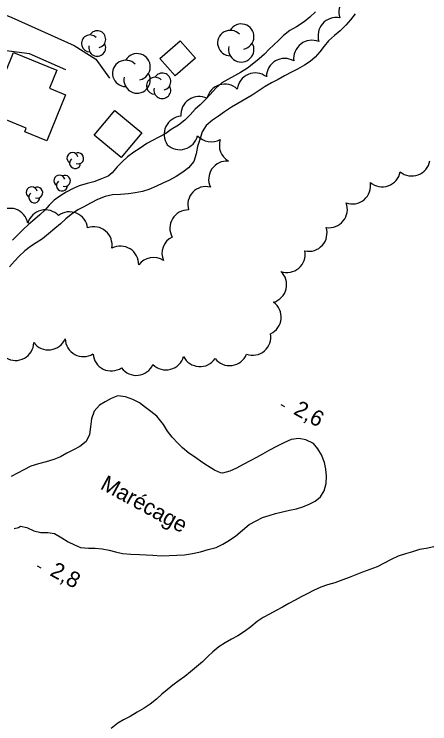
# Model space of a CAD drawing. Extents: x 219136 to 222520, y 5421589 to 5424530.
# Drawn here: x 220438.7 to 220517.5, y 5422818.4 to 5422953.1 of the extents above; entities that cross this region are included whole.
import ezdxf

# ---------------------------------------------------------------- set-up
doc = ezdxf.new("R2010")
doc.units = 0
for name, color, linetype in [('Level 19', 7, 'Continuous'), ('Level 2', 7, 'Continuous'), ('Level 3', 7, 'Continuous'), ('Level 31', 7, 'Continuous'), ('Level 4', 7, 'Continuous'), ('Level 44', 7, 'Continuous'), ('Level 7', 7, 'Continuous')]:
    doc.layers.add(name, color=color, linetype=linetype)

msp = doc.modelspace()

# ---------------------------------------------------------------- linework, layer by layer
at = {"layer": 'Level 19'}
for points in [[(220447.7, 5422966.82), (220446.62, 5422967.06), (220444.01, 5422965.73), (220441.58, 5422962.38), (220440.51, 5422959.82), (220439.56, 5422957.04), (220436.98, 5422955.8), (220434.73, 5422954.86), (220435.39, 5422953.58), (220438.23, 5422952.4), (220450.02, 5422947.09), (220454.18, 5422944.5), (220456.75, 5422940.92)], [(220448.49, 5422942.48), (220441.58, 5422945.53), (220436.18, 5422946.26), (220433.12, 5422945.86), (220429.86, 5422946.73)]]:
    msp.add_lwpolyline(points, dxfattribs=at)
at = {"layer": 'Level 2'}
for points in [[(220495.8, 5422953.51), (220494.73, 5422952.49), (220493.67, 5422951.59), (220492.19, 5422950.64), (220490.9, 5422949.94), (220489.74, 5422949.01), (220488.81, 5422948.12), (220487.89, 5422947.25), (220486.97, 5422946.35), (220486.09, 5422945.46), (220485.08, 5422944.61), (220484.1, 5422943.79), (220482.89, 5422942.81), (220481.56, 5422941.97), (220480.41, 5422941.34), (220479.18, 5422940.68), (220478.03, 5422940.04), (220476.87, 5422939.01), (220475.83, 5422937.83), (220474.94, 5422936.84), (220473.91, 5422935.87), (220472.98, 5422935.01), (220472.06, 5422933.99), (220471.03, 5422932.93), (220469.81, 5422932.02), (220468.46, 5422931.19), (220467.39, 5422930.45), (220466.07, 5422929.74), (220464.92, 5422929.12), (220463.83, 5422928.52), (220462.55, 5422927.64), (220461.37, 5422926.88), (220460.16, 5422925.97), (220459.13, 5422925.02), (220458.21, 5422924.09), (220457.22, 5422922.97), (220456.5, 5422922.35), (220455.2, 5422921.82), (220453.78, 5422921.28), (220452.5, 5422920.92), (220451.01, 5422920.5), (220449.85, 5422919.99), (220448.51, 5422919.28), (220447.35, 5422918.51), (220446.28, 5422917.76), (220445.31, 5422916.81), (220444.46, 5422915.85), (220443.56, 5422914.96), (220442.58, 5422914.14), (220441.39, 5422913.17), (220440.31, 5422912.16), (220439.39, 5422911.22)], [(220503.32, 5422953.13), (220502.42, 5422951.99), (220501.51, 5422950.98), (220500.48, 5422949.92), (220499.4, 5422948.99), (220498.25, 5422947.99), (220497.44, 5422946.96), (220496.59, 5422945.94), (220495.71, 5422944.93), (220494.8, 5422944.05)], [(220494.8, 5422944.05), (220493.7, 5422943.38), (220492.35, 5422942.65), (220491.21, 5422942.04), (220489.91, 5422941.34), (220488.71, 5422940.69), (220487.46, 5422940.02), (220486.24, 5422939.36), (220484.93, 5422938.48), (220483.77, 5422937.71), (220482.57, 5422936.97), (220481.07, 5422936.09), (220479.86, 5422935.44), (220478.53, 5422934.55), (220477.38, 5422933.7), (220476.24, 5422932.92), (220475.08, 5422931.95), (220474.32, 5422930.72), (220473.86, 5422929.29), (220473.43, 5422927.97), (220473.14, 5422926.55), (220472.74, 5422925.1), (220471.73, 5422923.92), (220470.67, 5422923.08), (220469.37, 5422922.27), (220468.09, 5422921.59), (220466.86, 5422920.98), (220465.62, 5422920.4), (220464.2, 5422919.8), (220462.97, 5422919.43), (220461.58, 5422919.17), (220460.32, 5422919), (220458.81, 5422918.84), (220457.3, 5422918.81), (220455.92, 5422918.48), (220454.48, 5422917.92), (220453.11, 5422917.21), (220451.85, 5422916.53), (220450.73, 5422915.91), (220449.49, 5422915.07), (220448.44, 5422914.21), (220447.44, 5422913.31), (220446.39, 5422912.38), (220445.15, 5422911.36), (220444.01, 5422910.44), (220442.84, 5422909.7), (220441.79, 5422909.01), (220440.7, 5422908.14), (220439.59, 5422907.12), (220438.73, 5422906.2), (220437.8, 5422905.14)], [(220439.39, 5422911.22), (220438.37, 5422910.16)]]:
    msp.add_lwpolyline(points, dxfattribs=at)
at = {"layer": 'Level 3'}
for p, q in [((220489.2, 5422879.03), (220489.9, 5422878.64)), ((220443.02, 5422848.42), (220443.72, 5422848.04))]:
    msp.add_line(p, q, dxfattribs=at)
at = {"layer": 'Level 31'}
for points in [[(220473.05, 5422944.73), (220469.19, 5422941.36), (220466.31, 5422944.66), (220470.16, 5422948.03)], [(220433.87, 5422934.35), (220438.55, 5422945.77), (220446.74, 5422942.41), (220445.35, 5422939.04), (220448.43, 5422937.77), (220444.83, 5422929.02), (220440.68, 5422930.72), (220440.97, 5422931.43)], [(220462.86, 5422930.57), (220458.94, 5422925.85), (220453.84, 5422930.1), (220457.76, 5422934.81)]]:
    msp.add_lwpolyline(points, close=True, dxfattribs=at)
at = {"layer": 'Level 4'}
for points in [[(220518.21, 5422851.98), (220516.76, 5422851.72), (220515.49, 5422851.47), (220514.16, 5422851.08), (220512.84, 5422850.67), (220511.48, 5422850.21), (220510.16, 5422849.6), (220508.81, 5422848.88), (220507.46, 5422848.2), (220506.06, 5422847.71), (220504.7, 5422847.22), (220503.41, 5422846.71), (220502.19, 5422846.21), (220500.98, 5422845.74), (220499.48, 5422845.2), (220498.09, 5422844.79), (220496.8, 5422844.36), (220495.44, 5422843.75), (220494.31, 5422843.16), (220493.09, 5422842.5), (220491.95, 5422841.89), (220490.76, 5422841.24), (220489.52, 5422840.58), (220488.32, 5422839.94), (220487.08, 5422839.26), (220485.86, 5422838.58), (220484.73, 5422837.81)], [(220484.73, 5422837.81), (220483.56, 5422836.86), (220482.34, 5422835.95), (220481.06, 5422835.12), (220479.87, 5422834.46), (220478.68, 5422833.82), (220477.44, 5422833.06), (220476.31, 5422832.08), (220475.41, 5422831.18), (220474.37, 5422830.22), (220473.21, 5422829.24), (220472.09, 5422828.31), (220471.05, 5422827.43), (220469.96, 5422826.62), (220468.77, 5422825.77), (220467.65, 5422824.87), (220466.66, 5422824.04), (220465.62, 5422823.12), (220464.43, 5422822.13), (220463.34, 5422821.38), (220461.99, 5422820.63), (220460.63, 5422819.85), (220459.42, 5422819.2), (220458.31, 5422818.53), (220457.07, 5422817.55)]]:
    msp.add_lwpolyline(points, dxfattribs=at)
at = {"layer": 'Level 44'}
for centre, radius, start, end in [((220503.67, 5422953.47), 3.46, 78.6697, 198.6697), ((220481.71, 5422948.79), 2.41, 282.2692, 149.7262), ((220499.72, 5422948.97), 3.46, 78.8019, 198.8019), ((220454.41, 5422948.3), 1.61, 282.2692, 149.7262), ((220479.64, 5422947.58), 2.41, 44.1153, 269.8039), ((220453.03, 5422947.5), 1.61, 44.1153, 269.8039), ((220454.41, 5422946.69), 1.61, 166.9368, 29.6212), ((220481.71, 5422946.38), 2.41, 166.9368, 29.6212), ((220495.11, 5422944.65), 3.46, 67.3897, 187.3897), ((220461.97, 5422943.07), 2.5, 282.2692, 149.7262), ((220489.94, 5422941.2), 3.46, 60.0102, 180.0102), ((220459.82, 5422941.82), 2.5, 44.1153, 269.8039), ((220461.97, 5422940.56), 2.5, 166.9368, 29.6212), ((220466.75, 5422940.27), 1.61, 282.2692, 149.7262), ((220484.39, 5422938.44), 3.46, 53.0049, 173.0049), ((220465.37, 5422939.47), 1.61, 44.1153, 269.8039), ((220466.75, 5422938.66), 1.61, 166.9368, 29.6212), ((220478.59, 5422936.33), 3.46, 47.0027, 167.0027), ((220473.73, 5422933.98), 3.46, 64.5457, 184.5457), ((220470.54, 5422930.25), 3.46, 94.3395, 214.3395), ((220470.06, 5422930.81), 3.46, 226.5012, 346.5012), ((220476.03, 5422932.29), 3.46, 221.4231, 299.6204), ((220481.02, 5422928.18), 3.46, 161.4231, 239.6204), ((220449.73, 5422925.74), 1.05, 14.9746, 237.6589), ((220450.22, 5422924.82), 1.05, 130.3069, 357.764), ((220450.77, 5422925.7), 1.05, 252.1531, 117.8417), ((220478.99, 5422921.73), 3.46, 85.2897, 205.2897), ((220514.04, 5422925.82), 3.46, 230.494, 350.494), ((220508.43, 5422923.76), 3.46, 229.6758, 349.6758), ((220447.24, 5422921.48), 1.05, 14.9746, 237.6589), ((220448.28, 5422921.44), 1.05, 252.1531, 117.8417), ((220442, 5422919.24), 1.05, 14.9746, 237.6589), ((220443.04, 5422919.2), 1.05, 252.1531, 117.8417), ((220447.73, 5422920.56), 1.05, 130.3069, 357.764), ((220475.04, 5422916.89), 3.46, 76.4089, 196.4089), ((220502.78, 5422920.51), 3.46, 250.196, 10.196), ((220442.49, 5422918.32), 1.05, 130.3069, 357.764), ((220437.85, 5422912.77), 3.46, 10.9192, 130.9192), ((220498.37, 5422916.01), 3.46, 260.9109, 20.9109), ((220444.58, 5422912.47), 3.46, 43.9002, 163.9002), ((220449.16, 5422912.1), 3.46, 7.001, 127.001), ((220471.64, 5422912.45), 3.46, 88.798, 208.798), ((220453.77, 5422909.27), 3.46, 349.8848, 109.8848), ((220494.52, 5422911.53), 3.46, 257.8742, 17.8742), ((220470.15, 5422907.68), 3.46, 116.4651, 203.2874), ((220458.82, 5422905.6), 3.46, 358.1356, 118.1356), ((220490.39, 5422907.51), 3.46, 250.5024, 10.5024), ((220465.06, 5422903.42), 3.46, 56.4651, 143.2874), ((220486.85, 5422901.73), 3.46, 286.5572, 46.5572), ((220485.83, 5422895.59), 3.46, 294.5875, 54.5875), ((220483.86, 5422891.81), 3.46, 250.4143, 10.4143), ((220438.93, 5422890.82), 3.46, 238.8226, 358.8226), ((220445.17, 5422892.83), 3.46, 216.8588, 336.8588), ((220451.81, 5422891.55), 3.46, 181.3094, 301.3094), ((220457.07, 5422888.83), 3.46, 184.0611, 304.0611), ((220467.43, 5422889.03), 3.46, 224.9135, 344.9135), ((220473.89, 5422889.65), 3.46, 206.0536, 326.0536), ((220479.49, 5422889.85), 3.46, 217.9389, 337.9389), ((220461.81, 5422888), 3.46, 215.9946, 335.9946)]:
    msp.add_arc(centre, radius, start, end, dxfattribs=at)
at = {"layer": 'Level 7'}
for points in [[(220477.81, 5422866.02), (220476.66, 5422866.55), (220475.33, 5422867.37), (220474.27, 5422868.09), (220473.07, 5422868.98), (220471.79, 5422869.79), (220470.6, 5422870.77), (220469.67, 5422871.69), (220468.61, 5422872.79), (220467.74, 5422873.95), (220466.96, 5422875.19), (220465.7, 5422876.82), (220464.6, 5422877.65), (220463.54, 5422878.41), (220462.44, 5422879.33), (220461.17, 5422879.98), (220459.8, 5422880.49), (220458.29, 5422880.67), (220457.04, 5422880.12), (220455.93, 5422879.52), (220454.82, 5422878.87), (220453.81, 5422877.74), (220453.34, 5422876.29), (220453.15, 5422874.76), (220452.92, 5422873.29), (220452.3, 5422871.98), (220451.12, 5422871.06), (220449.92, 5422870.41), (220448.67, 5422869.76), (220447.45, 5422869.1), (220446.21, 5422868.59), (220444.75, 5422868.12), (220443.29, 5422867.76), (220441.85, 5422867.32), (220440.49, 5422866.6), (220439.32, 5422865.98), (220438.13, 5422865.34)], [(220441.05, 5422855.65), (220442.38, 5422855.06), (220443.73, 5422854.75), (220445.06, 5422854.74), (220446.34, 5422854.54), (220447.68, 5422853.69), (220448.9, 5422852.96), (220450.09, 5422852.36), (220451.27, 5422851.91), (220452.76, 5422851.74), (220454.01, 5422851.73), (220455.35, 5422851.6), (220456.65, 5422851.35), (220457.88, 5422851.03), (220459.23, 5422850.76), (220460.78, 5422850.61), (220462.41, 5422850.54), (220463.67, 5422850.51), (220464.93, 5422850.44), (220466.52, 5422850.33), (220468.04, 5422850.35), (220469.52, 5422850.4), (220470.97, 5422850.49), (220472.48, 5422850.73), (220474, 5422851.07), (220475.47, 5422851.47), (220476.93, 5422851.91), (220478.23, 5422852.52), (220479.51, 5422853.24), (220480.7, 5422854.11), (220481.97, 5422855.18), (220483.21, 5422856.22), (220484.52, 5422856.97), (220485.77, 5422857.55), (220486.98, 5422857.96), (220488.22, 5422858.34), (220489.55, 5422858.67), (220490.89, 5422858.94), (220492.18, 5422859.24), (220493.4, 5422859.58), (220494.6, 5422860.08), (220495.73, 5422860.7), (220496.73, 5422861.51), (220497.43, 5422862.66), (220497.83, 5422864.01), (220497.87, 5422865.4), (220497.75, 5422866.71), (220497.49, 5422868.01), (220496.91, 5422869.44), (220496.25, 5422870.62), (220495.39, 5422871.59), (220493.98, 5422872.31), (220492.66, 5422872.56), (220491.2, 5422872.38), (220489.78, 5422871.75), (220488.42, 5422871.03), (220487.1, 5422870.32), (220485.75, 5422869.59), (220484.63, 5422868.98), (220483.4, 5422868.32), (220482.1, 5422867.62), (220480.8, 5422866.94), (220479.56, 5422866.35), (220478.19, 5422865.97), (220477.81, 5422866.02)], [(220438.67, 5422855.51), (220439.5, 5422855.7), (220439.88, 5422855.9), (220441.05, 5422855.65)]]:
    msp.add_lwpolyline(points, dxfattribs=at)

# ---------------------------------------------------------------- texts
at = {"layer": 'Level 3'}
for s, p in [('2,6', (220491.44, 5422877.29)), ('2,8', (220445.26, 5422846.68))]:
    msp.add_text(s, height=3, rotation=331.383, dxfattribs=at).set_placement(p)
at = {"layer": 'Level 7'}
msp.add_text('Marécage', height=3, rotation=331.383, dxfattribs=at).set_placement((220454.8, 5422863.1))

doc.saveas('drawing.dxf')
